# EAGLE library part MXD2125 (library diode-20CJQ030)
MEMSIC's MXD2125 G/H M/N FEATURES: Resolution better than 1 milli-g Dual axis accelerometer fabricated on a monolithic CMOS IC On chip mixed mode signal processing No moving parts 50,000 g shock survival rating 17 Hz bandwidth expandable to >160 Hz 3.0V to 5.25V single supply continuous operation Continuous self test Independent axis programmability (special order) Compensated for Sensitivity over temperature Ultra low initial Zero-g Offset APPLICATIONS: Automotive: Vehicle Security/Vehicle stability control/ Headlight Angle Control/Tilt Sensing Security: Gas Line/Elevator/Fatigue Sensing Information Appliances Computer Peripherals/PDA?s/Mouse Smart Pens/Cell Phones Gaming: Joystick/RF Interface/Menu Selection/Tilt Sensing GPS: electronic Compass tilt Correction Consumer: LCD projectors, pedometers, blood pressure Monitor, digital cameras GENERAL DESCRIPTION The MXD2125G/H/M/N is a low cost, dual axis accelerometer fabricated on a standard, submicron CMOS process. It is a complete sensing system with on-chip mixed mode signal processing. The MXD2125G/H/M/N measures acceleration with a full-scale range of ±3 g and a sensitivity of 12.5%/g @5V at 25°C. It can measure both dynamic acceleration (e.g. vibration) and static acceleration (e.g. gravity). The MXD2125G/H/M/N design is based on heat convection and requires no solid proof mass. This eliminates stiction and particle problems associated with competitive devices and provides shock survival of 50,000 g, leading to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
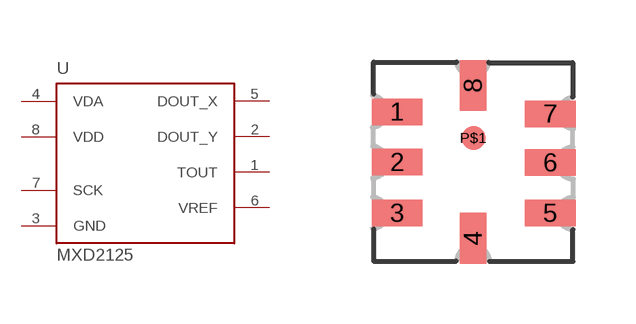
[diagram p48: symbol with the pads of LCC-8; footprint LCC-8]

Designator prefix U

## MXD2125  [LCC-8]
1  TOUT  out
2  DOUT_Y  out
3  GND  pwr
4  VDA  pwr
5  DOUT_X  out
6  VREF  out
7  SCK  in
8  VDD  pwr

## Footprint LCC-8 (pad centres in mm)
LEADED CHIP CARRIER
smd 1.27 x 0.66: 1 -1.91,1.25; 2 -1.91,-0.01; 3 -1.91,-1.28; 5 1.92,-1.28; 6 1.92,-0.02; 7 1.92,1.2
smd 0.66 x 1.27: 4 -0.01,-1.91; 8 -0.01,1.91
smd 0.6 x 0.6: P$1 0,0.6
